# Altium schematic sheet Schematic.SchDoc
size A4; SheetNumber: 1; SheetTotal: 3
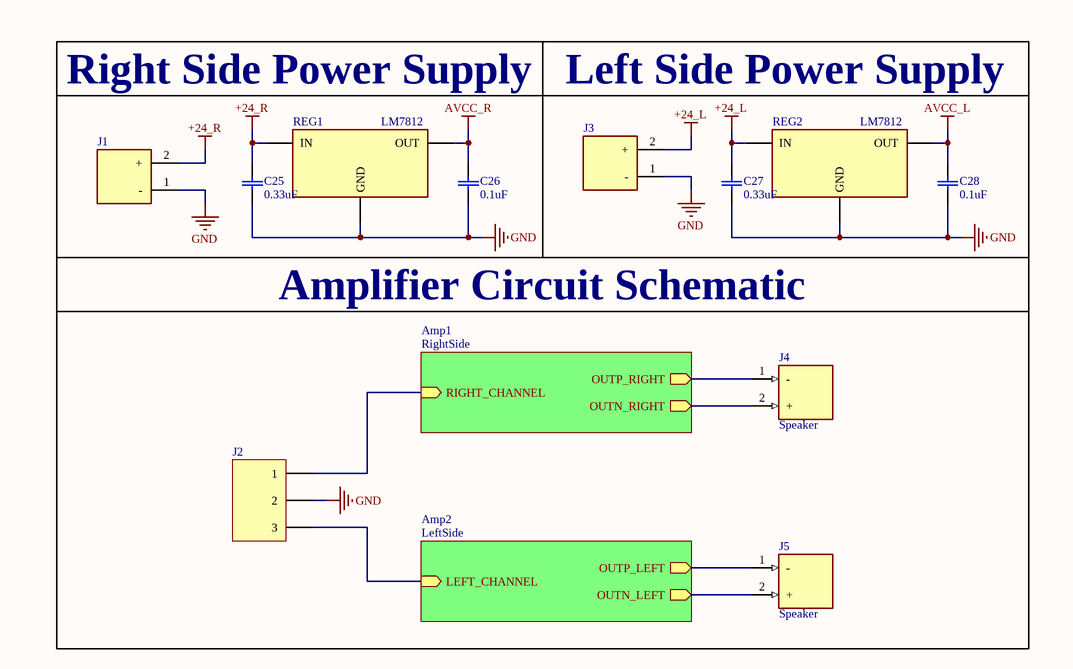
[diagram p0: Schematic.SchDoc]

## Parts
C25  0.33uF  [CERAMIC0805]
C26  0.1uF  [CERAMIC0805]
C27  0.33uF  [CERAMIC0805]
C28  0.1uF  [CERAMIC0805]
J1  Borne KF301-2P  [Borne KF301-2P]  (value not drawn)
J2  Borne KF301-3P  [Borne KF301-3P]  (value not drawn)
J3  Borne KF301-2P  [Borne KF301-2P]  (value not drawn)
J4  Speaker  [Borne KF301-2P]
J5  Speaker  [Borne KF301-2P]
REG1  LM7812  [TO-220-3]
REG2  LM7812  [TO-220-3]

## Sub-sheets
Amp1 = RightSide: RIGHT_CHANNEL (in), OUTP_RIGHT (out), OUTN_RIGHT (out)
Amp2 = LeftSide: LEFT_CHANNEL (in), OUTP_LEFT (out), OUTN_LEFT (out)

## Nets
+24_L: C27.2(C2) J3.2(+) REG2.1(IN)
+24_R: C25.2(C2) J1.2(+) REG1.1(IN)
AVCC_L: C28.2(C2) REG2.3(OUT)
AVCC_R: C26.2(C2) REG1.3(OUT)
GND: C25.1(C1) C26.1(C1) C27.1(C1) C28.1(C1) J1.1(-) J2.2 J3.1(-) REG1.2(GND) REG2.2(GND)
NetJ2_1: J2.1 ; sheet Amp1/RIGHT_CHANNEL
NetJ2_3: J2.3 ; sheet Amp2/LEFT_CHANNEL
NetJ4_1: J4.1(-) ; sheet Amp1/OUTP_RIGHT
NetJ4_2: J4.2(+) ; sheet Amp1/OUTN_RIGHT
NetJ5_1: J5.1(-) ; sheet Amp2/OUTP_LEFT
NetJ5_2: J5.2(+) ; sheet Amp2/OUTN_LEFT

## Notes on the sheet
- Right Side Power Supply
- Left Side Power Supply
- Amplifier Circuit Schematic

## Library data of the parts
C25-C28 = Cap: MF: KEMET; MP: TAJC226M025RNJ
J1 J3-J5 = Borne KF301-2P: 2 Pin Terminal Block 5mm Pitch
REG1 REG2 = LM78XX: Regulador de tensão linha LM78XX; MP: LM7805S/NOPB; MF: Texas Instruments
